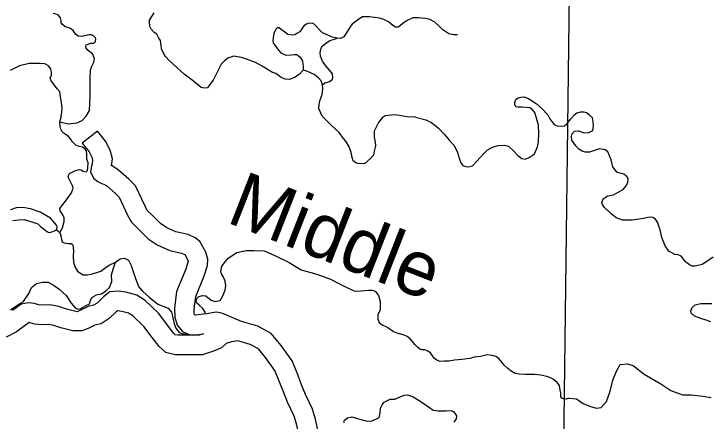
# Model space of a CAD drawing. Extents: x 8749 to 11879, y 13275 to 15339.
# Drawn here: x 9703.5 to 9809.8, y 14207.1 to 14269.4 of the extents above; entities that cross this region are included whole.
import ezdxf

# ---------------------------------------------------------------- set-up
doc = ezdxf.new("R2010")
doc.units = 0
for name, color, linetype in [('Level 35', 7, 'Continuous'), ('Level 46', 7, 'Continuous'), ('Level 5', 7, 'Continuous')]:
    doc.layers.add(name, color=color, linetype=linetype)

msp = doc.modelspace()

# ---------------------------------------------------------------- linework, layer by layer
at = {"layer": 'Level 35'}
for points in [[(9710.56, 14252.92), (9711.82, 14252.57), (9713.12, 14252.73), (9713.94, 14253.11), (9714.55, 14253.75), (9715.07, 14254.65), (9715.17, 14256.86), (9715.17, 14259.71), (9715.23, 14260.79), (9715.43, 14261.39), (9715.75, 14262.03), (9715.85, 14262.61), (9715.53, 14263.31), (9714.89, 14263.81), (9714.59, 14264.19), (9714.53, 14264.4), (9714.53, 14264.46), (9714.57, 14264.68), (9714.87, 14264.8), (9715.23, 14264.92), (9715.75, 14264.92), (9716.01, 14265.2), (9716.07, 14265.54), (9715.99, 14265.76), (9715.69, 14266.04), (9715.35, 14266.22), (9715.03, 14266.22), (9714.79, 14266.18), (9714.39, 14266.08), (9713.86, 14265.98), (9713.38, 14266.02), (9712.98, 14266.28), (9712.78, 14266.56), (9712.56, 14266.88), (9712.2, 14267.16), (9711.78, 14267.32), (9711.35, 14267.42), (9710.97, 14267.77), (9710.75, 14268.05), (9710.77, 14268.39), (9710.65, 14268.81), (9710.29, 14269.25), (9709.93, 14269.37), (9709.51, 14269.47)], [(9729.55, 14260.17), (9728.4, 14261.26), (9727.33, 14262.25), (9726.69, 14262.91), (9726.33, 14263.51), (9726.09, 14264.05), (9726.03, 14264.57), (9725.93, 14265.32), (9725.7, 14265.72), (9725.38, 14266.3), (9724.96, 14266.58), (9724.5, 14267.07), (9724.36, 14267.39), (9724.3, 14267.67), (9724.24, 14268.05), (9724.28, 14268.45), (9724.64, 14269.03), (9724.98, 14269.57)], [(9756.82, 14268.94), (9756.26, 14268.6), (9755.23, 14267.83), (9754.97, 14267.43), (9754.43, 14266.61), (9753.99, 14265.91), (9753.46, 14265.65), (9752.94, 14265.69), (9752.2, 14265.83), (9751.44, 14266.21), (9750.71, 14266.53), (9750.25, 14266.95), (9749.81, 14267.47), (9749.39, 14267.87), (9749.11, 14267.97), (9748.54, 14267.95), (9748.28, 14267.85), (9747.86, 14267.61), (9747.56, 14267.15), (9747.24, 14266.69), (9746.78, 14266.39), (9746.5, 14266.21), (9746.2, 14266.17)], [(9771.38, 14266.23), (9770.82, 14266.23), (9770.02, 14266.35), (9769.11, 14266.95), (9768.59, 14267.49), (9767.87, 14268.17), (9767.15, 14268.56), (9766.42, 14268.72), (9765.38, 14268.8), (9764.54, 14268.82), (9763.67, 14268.42), (9763.01, 14267.93), (9762.37, 14267.45), (9762.2, 14267.39), (9761.9, 14267.37), (9761.46, 14267.65), (9760.81, 14268.21), (9760.09, 14268.56), (9759.41, 14268.78), (9757.9, 14268.98), (9756.82, 14268.94)], [(9746.2, 14266.17), (9745.43, 14266.27), (9744.93, 14266.61), (9744.39, 14267.02), (9744.07, 14267.26), (9743.79, 14267.26), (9743.56, 14267.06), (9743.28, 14266.39), (9743.16, 14265.73), (9743.12, 14265.33), (9743.16, 14265.01), (9743.44, 14264.65), (9744.01, 14263.85), (9744.35, 14263.48), (9745.09, 14263.1), (9745.91, 14263.14), (9746.36, 14263.2), (9746.74, 14263.22), (9746.8, 14263.21)], [(9750.73, 14258.58), (9751.05, 14258.86), (9751.82, 14259.08), (9752.22, 14259.44), (9752.28, 14259.74), (9752.24, 14260.22), (9751.82, 14260.76), (9751.19, 14261.51), (9750.69, 14262.19), (9750.43, 14262.97), (9750.37, 14263.47), (9750.45, 14264.01), (9750.63, 14264.41), (9751.15, 14264.86), (9751.86, 14265.32), (9752.56, 14265.54), (9752.94, 14265.69)], [(9746.8, 14263.21), (9747.3, 14262.78), (9747.68, 14262.2), (9747.76, 14261.36), (9747.76, 14260.82), (9747.22, 14260.21), (9746.52, 14259.71), (9745.69, 14259.39), (9744.99, 14259.41), (9744.39, 14259.69), (9743.58, 14260.29), (9743.06, 14260.46), (9741.48, 14261.4), (9740.45, 14262), (9739.07, 14262.48), (9738.34, 14262.74), (9737.72, 14262.86), (9737.12, 14262.92), (9736.7, 14262.8), (9736.23, 14262.62), (9735.69, 14262.18), (9735.21, 14261.7), (9734.55, 14260.4), (9733.98, 14259.25), (9733.48, 14258.59), (9733.12, 14258.11), (9732.64, 14258.07), (9732.18, 14258.17), (9731.53, 14258.67), (9730.59, 14259.41), (9729.55, 14260.17)], [(9710.57, 14235.97), (9710.94, 14236.68), (9711.2, 14237.67), (9711.2, 14238.23), (9710.94, 14238.79), (9710.58, 14239.27), (9710.56, 14239.65), (9710.84, 14240.04), (9711.58, 14240.94), (9712.31, 14242.02), (9712.57, 14242.74), (9712.47, 14243.11), (9712.21, 14243.63), (9711.92, 14244.21), (9711.8, 14244.57), (9712.02, 14244.97), (9712.85, 14245.41), (9713.51, 14245.59), (9713.81, 14245.57), (9714.11, 14245.37), (9714.57, 14245.27), (9714.8, 14245.45), (9714.84, 14245.89), (9714.86, 14246.6), (9714.68, 14247.21), (9714.68, 14247.92), (9714.62, 14248.48), (9714.39, 14248.78), (9714.01, 14249.02), (9713.51, 14249.1), (9712.97, 14249.34), (9712.49, 14249.84), (9712.17, 14250.32), (9711.84, 14250.72), (9711.38, 14250.99), (9711.04, 14251.21), (9710.96, 14251.31), (9710.7, 14251.76), (9710.6, 14252.18), (9710.56, 14252.92), (9710.76, 14253.62), (9710.88, 14254.91), (9710.82, 14255.91), (9710.66, 14256.71), (9710.56, 14257.47), (9710.16, 14257.96), (9709.59, 14258.71), (9709.21, 14259.17), (9709.09, 14259.59), (9709.25, 14260.05), (9709.27, 14260.37), (9709.17, 14261.01), (9708.81, 14261.49), (9708.26, 14261.76), (9707.46, 14261.82), (9705.83, 14261.8), (9704.37, 14261.49), (9702.96, 14260.75)], [(9750.31, 14256.12), (9750.67, 14257.09), (9750.75, 14257.93), (9750.73, 14258.58), (9750.53, 14259.16), (9750.09, 14259.64), (9749.43, 14260.12), (9748.34, 14260.64), (9747.76, 14260.82)], [(9764.93, 14253.63), (9763.61, 14253.67), (9762.48, 14253.87), (9761.66, 14253.95), (9761.14, 14253.93), (9760.29, 14253.81), (9759.83, 14253.49), (9759.29, 14252.77), (9758.61, 14251.46), (9758.63, 14250.54), (9758.79, 14249.8), (9758.81, 14249.21), (9758.63, 14248.41), (9758.53, 14247.81), (9758.06, 14247.29), (9757.2, 14246.53), (9756.6, 14246.45), (9756.14, 14246.53), (9755.79, 14246.61), (9755.41, 14246.91), (9755.25, 14247.43), (9755.11, 14248.21), (9754.77, 14249.07), (9754.27, 14249.92), (9753.93, 14250.36), (9753.24, 14251.28), (9752.06, 14252.38), (9751.15, 14253.25), (9750.67, 14253.77), (9750.35, 14254.47), (9750.17, 14254.93), (9750.19, 14255.51), (9750.31, 14256.12)], [(9779.14, 14249.17), (9779.93, 14248.47), (9780.61, 14247.75), (9781.2, 14247.28), (9781.68, 14247.2), (9782.12, 14247.34), (9782.24, 14247.38), (9783.12, 14248.01), (9783.57, 14249.07), (9783.73, 14249.85), (9783.81, 14251.1), (9783.75, 14252.4), (9783.43, 14253.44), (9783.18, 14254.33), (9782.82, 14254.71), (9782.42, 14255.03), (9781.9, 14255.09), (9781.24, 14255.13), (9780.61, 14255.13), (9780.27, 14255.21), (9780.13, 14255.53), (9780.15, 14255.93), (9780.29, 14256.29), (9780.65, 14256.59), (9781.04, 14256.67), (9781.5, 14256.71), (9782.24, 14256.47), (9783.39, 14255.69), (9784.25, 14254.95), (9785.15, 14253.99), (9785.49, 14253.38), (9785.92, 14252.76), (9786.14, 14252.48), (9786.58, 14252.28), (9787.22, 14252.24), (9787.72, 14252.28), (9788.15, 14252.64), (9788.69, 14253.38), (9789.17, 14253.85)], [(9794.85, 14247.09), (9794.33, 14248.29), (9793.96, 14248.61), (9793.07, 14248.75), (9792.31, 14248.51), (9791.53, 14248.26), (9790.86, 14248.26), (9790.42, 14248.4), (9789.91, 14248.7), (9789.48, 14249.23), (9788.83, 14250.07), (9788.81, 14250.61), (9788.83, 14250.99), (9789.26, 14251.47), (9789.86, 14251.53), (9790.72, 14251.23), (9791.42, 14251.26), (9792.04, 14251.58), (9792.15, 14252.26), (9792.12, 14252.9), (9791.99, 14253.5), (9791.48, 14253.96), (9791.07, 14254.28), (9790.75, 14254.36), (9790.15, 14254.36), (9789.59, 14254.2), (9789.17, 14253.85)], [(9764.93, 14253.63), (9766.51, 14253.2), (9767.4, 14252.78), (9768.44, 14251.94), (9769.38, 14250.96), (9770.07, 14250.11), (9770.83, 14249.27), (9771.35, 14248.19), (9771.67, 14247.16), (9771.89, 14246.6), (9772.2, 14246.24), (9772.66, 14246.04), (9773.02, 14246.02), (9773.64, 14246.16), (9774.3, 14246.9), (9775.37, 14248.03), (9775.91, 14248.55), (9776.69, 14249.03), (9777.6, 14249.29), (9778.56, 14249.33), (9779.14, 14249.17)], [(9804.58, 14232.61), (9803.66, 14233.09), (9803.12, 14233.92), (9802.61, 14235.22), (9802.37, 14236.38), (9802.1, 14237.08), (9801.99, 14237.43), (9801.64, 14238), (9801.21, 14238.27), (9800.67, 14238.29), (9799.81, 14238.11), (9798.81, 14237.94), (9798.05, 14237.86), (9796.6, 14237.86), (9795.65, 14238.21), (9794.87, 14238.81), (9793.85, 14239.78), (9793.52, 14240.26), (9793.44, 14240.56), (9793.63, 14241.13), (9794.36, 14241.56), (9795.22, 14241.75), (9795.92, 14242.13), (9796.68, 14242.56), (9797.08, 14243.04), (9797.43, 14243.61), (9797.46, 14244.1), (9797.33, 14244.47), (9796.81, 14244.88), (9796.19, 14245.04), (9795.73, 14245.18), (9795.47, 14245.53), (9795.14, 14245.99), (9795.03, 14246.44), (9794.85, 14247.09)], [(9703.38, 14237.78), (9704.26, 14237.92), (9705.11, 14237.94), (9706.09, 14237.64), (9707.16, 14237.3), (9707.6, 14236.88), (9708.2, 14236.44), (9708.56, 14236.1), (9708.88, 14235.98), (9709.18, 14236.02), (9709.71, 14236.2), (9710.03, 14236.38), (9710.15, 14236.74), (9710.07, 14237.06), (9709.14, 14238.17), (9707.54, 14239.07), (9706.05, 14239.61), (9704.87, 14239.77), (9703.87, 14239.76), (9703.02, 14239.45)], [(9710.03, 14236.38), (9710.57, 14235.97), (9710.75, 14235.31), (9710.79, 14234.91), (9710.89, 14234.55), (9711.21, 14234.37), (9711.84, 14234.27), (9712.3, 14234.29), (9712.48, 14234.15), (9712.6, 14233.89), (9712.58, 14233.56), (9712.62, 14233.2), (9712.56, 14232.3), (9712.66, 14231.45), (9712.82, 14230.73), (9713.27, 14230.07), (9713.61, 14229.77), (9714.13, 14229.47), (9714.77, 14229.47), (9715.35, 14229.59), (9716.18, 14229.83), (9716.8, 14230.03), (9717.44, 14230.49), (9718.09, 14230.97), (9719.05, 14231.45)], [(9735.19, 14230.02), (9735.32, 14230.83), (9736.29, 14232.02), (9737.62, 14232.89), (9739.05, 14233.21), (9740.27, 14233.21), (9741.77, 14233.17), (9743.4, 14232.47), (9745.6, 14231.36), (9747.45, 14230.27), (9749.85, 14229.58), (9751.94, 14228.81), (9753.23, 14228.15), (9754.35, 14227.59), (9755.67, 14226.99), (9756.61, 14227.06), (9757.8, 14227.13), (9758.32, 14227.13), (9758.77, 14226.99), (9759.3, 14226.3), (9759.51, 14225.42), (9759.54, 14224.1), (9759.16, 14223.44), (9759.16, 14222.7), (9759.4, 14222.18), (9759.82, 14221.83), (9760.73, 14221.41), (9761.56, 14220.82), (9762.33, 14220.49)], [(9810.48, 14232.18), (9809.78, 14231.75), (9808.76, 14231.07), (9807.73, 14230.83), (9807.25, 14230.83), (9806.84, 14231.02), (9806.22, 14231.5), (9805.79, 14232.07), (9805.55, 14232.34), (9805.12, 14232.53), (9804.58, 14232.61)], [(9719.05, 14231.45), (9719.78, 14231.94), (9720.44, 14232.05), (9721.07, 14231.73), (9721.45, 14230.93), (9722.08, 14229.08), (9722.6, 14227.72), (9723.2, 14226.99), (9724.21, 14226.08), (9725.53, 14225), (9727.13, 14224.37), (9727.61, 14223.76), (9727.8, 14223.17), (9727.99, 14222.2), (9728.23, 14221.44), (9728.53, 14220.95), (9728.8, 14220.68), (9729.24, 14220.51), (9729.62, 14220.44), (9730.3, 14220.37)], [(9703.02, 14224.11), (9704.26, 14224.98), (9704.97, 14225.4), (9705.81, 14226.64), (9706.23, 14227.54), (9706.99, 14228.17), (9707.9, 14228.38), (9708.77, 14228.38), (9709.68, 14227.86), (9710.45, 14227.3), (9711.53, 14226.32), (9712.29, 14225.14), (9712.87, 14224.43), (9713.3, 14224.21), (9713.8, 14224.33), (9713.9, 14224.43), (9714.65, 14224.83), (9715.05, 14225.02), (9715.15, 14225.21), (9715.22, 14225.56), (9715.46, 14226.04), (9716.16, 14226.43), (9716.93, 14226.57), (9717.56, 14227.06), (9718.15, 14227.54), (9718.5, 14228.49), (9718.43, 14229.5), (9718.71, 14230.34), (9719.05, 14231.45)], [(9732.7, 14223.5), (9732.78, 14223.78), (9732.4, 14224.33), (9731.84, 14224.82), (9731.5, 14225.16), (9731.4, 14225.4), (9731.49, 14225.87), (9731.81, 14226.15), (9732.36, 14226.32), (9732.89, 14226.25), (9733.69, 14225.59), (9734.31, 14225.42), (9735.05, 14225.56), (9735.47, 14226.25), (9735.85, 14227.13), (9735.92, 14227.86), (9735.85, 14228.52), (9735.57, 14229.15), (9735.29, 14229.64), (9735.19, 14230.02)], [(9810.08, 14222.28), (9809.4, 14222.57), (9808.59, 14222.79), (9807.62, 14223.14), (9807.08, 14223.6), (9807.03, 14224), (9807.25, 14224.49), (9807.73, 14224.89), (9808.57, 14225.11), (9809.65, 14225.11), (9810.24, 14225.11)], [(9788.41, 14210.6), (9787.96, 14210.44), (9787.6, 14210.5), (9787.34, 14210.62), (9787.16, 14210.84), (9787.14, 14211.04), (9787.14, 14211.44), (9787.06, 14211.86), (9786.94, 14212.54), (9786.58, 14213), (9786, 14213.53), (9785.25, 14213.89), (9784.13, 14214.11), (9783.18, 14214.23), (9781.78, 14214.25), (9780.79, 14214.31), (9780.19, 14214.39), (9779.55, 14214.75), (9779.07, 14215.13), (9778.5, 14215.67), (9778, 14216.34), (9777.64, 14216.72), (9777.24, 14217), (9776.68, 14217.16), (9775.91, 14217.22), (9774.89, 14217), (9773.93, 14216.88), (9773.24, 14216.66), (9772.01, 14216.54), (9770.89, 14216.42), (9770.1, 14216.3), (9769.38, 14216.28), (9768.68, 14216.24), (9768.18, 14216.42), (9767.81, 14216.72), (9767.63, 14216.96), (9767.41, 14217.26), (9767.25, 14217.56), (9766.83, 14217.82), (9766.39, 14218), (9765.93, 14218.02), (9765.55, 14218.18), (9765.24, 14218.4), (9764.82, 14218.84), (9764.44, 14219.32), (9764.1, 14219.67), (9763.64, 14220.05), (9763.18, 14220.27), (9762.33, 14220.49)], [(9788.41, 14210.6), (9789.56, 14210.51), (9790.6, 14209.8), (9791.69, 14209.33), (9792.63, 14209.09), (9793.34, 14209.19), (9794.14, 14210.13), (9794.71, 14211.69), (9795.13, 14213.39), (9795.7, 14214.76), (9796.22, 14215.75), (9797.3, 14215.89), (9798.25, 14215.61), (9799.9, 14214.29), (9802.44, 14212.82), (9804, 14211.78), (9805.75, 14211.12), (9807.11, 14211.12), (9808.86, 14210.93), (9810.13, 14210.74)], [(9754, 14206.88), (9754.1, 14207.23), (9754.55, 14207.61), (9755.18, 14207.75), (9756.23, 14207.47), (9757.55, 14207.09), (9758.32, 14207.16), (9759.36, 14207.65), (9759.54, 14208.35), (9759.57, 14209.08), (9759.82, 14209.6), (9760.13, 14210.02), (9761.04, 14210.44), (9761.77, 14210.48), (9762.57, 14210.82), (9763.2, 14211.07), (9763.72, 14211.1), (9764.56, 14210.82), (9765.77, 14210.09), (9767.1, 14209.18), (9767.62, 14208.8), (9768.42, 14208.66), (9769.64, 14208.7), (9770.41, 14208.73), (9770.76, 14208.56), (9771, 14208.24), (9771.21, 14207.89), (9771.17, 14207.44), (9770.82, 14206.95)]]:
    msp.add_lwpolyline(points, dxfattribs=at)
at = {"layer": 'Level 46'}
for points in [[(9722.14, 14243.09), (9721.1, 14244.13), (9719.53, 14245.48), (9718.53, 14246.15), (9718.47, 14246.17), (9718.59, 14247.24), (9718.25, 14248.55), (9717.55, 14249.93), (9716.32, 14251.47), (9713.97, 14249.61)], [(9713.97, 14249.61), (9715.01, 14248.3), (9715.43, 14247.47), (9715.55, 14247.02), (9715.49, 14246.46), (9715.4, 14246.1), (9715.23, 14245.25), (9715.7, 14244.3), (9716.34, 14243.76), (9716.9, 14243.48), (9717.28, 14243.38), (9717.71, 14243.09), (9719.06, 14241.93), (9719.64, 14241.35)], [(9750.1, 14205.19), (9749.65, 14207.42), (9749.18, 14208.92), (9748.13, 14211.18), (9747.52, 14212.65), (9747, 14214.08), (9746.06, 14216.32), (9744.39, 14218.65), (9742.86, 14220.5), (9740.81, 14221.64), (9738.34, 14222.34), (9735.32, 14223.61), (9734.45, 14223.79), (9732.97, 14223.53), (9731.27, 14223.31), (9731.18, 14223.31), (9731.11, 14223.53), (9731.07, 14224.28), (9731.32, 14226.16), (9732.62, 14229.34), (9733.12, 14230.91), (9733.16, 14231.89), (9732.89, 14232.97), (9731.95, 14234.6), (9731.25, 14235.14), (9730.16, 14235.66), (9728.3, 14236.08), (9726.9, 14236.7), (9725.94, 14237.34), (9724.7, 14238.58), (9723.92, 14239.35), (9723.57, 14239.99), (9722.14, 14243.09)], [(9719.64, 14241.35), (9720.89, 14238.64), (9721.5, 14237.52), (9722.59, 14236.45), (9724.03, 14235.01), (9725.45, 14234.06), (9727.35, 14233.22), (9729.17, 14232.81), (9729.65, 14232.58), (9730.08, 14231.84), (9730.15, 14231.58), (9730.14, 14231.43), (9729.8, 14230.37), (9728.39, 14226.94), (9728.06, 14224.39), (9728.14, 14223), (9728.51, 14221.77), (9729.32, 14220.83), (9730.3, 14220.36), (9731.37, 14220.29), (9732.52, 14220.45)], [(9732.52, 14220.45), (9731.86, 14220.23), (9730.51, 14220.23), (9728.59, 14220.23), (9728.2, 14220.33), (9727.94, 14220.56), (9727.07, 14221.73), (9725.61, 14223.6), (9723.6, 14225.54), (9722.32, 14226.39), (9720.66, 14226.83), (9719.46, 14227.01), (9718.21, 14226.87), (9717.21, 14226.1), (9716.23, 14225.16), (9715.71, 14224.82), (9714.9, 14224.66), (9713.61, 14224.01), (9713.19, 14223.84)], [(9713.19, 14223.84), (9711.58, 14224.24), (9710.39, 14224.65), (9709.06, 14224.88), (9707.93, 14224.84), (9707.3, 14224.89), (9706.66, 14225.09), (9705.76, 14225.21), (9704.63, 14225), (9703.32, 14224.05)], [(9737.77, 14219.39), (9736.82, 14219.21), (9735.99, 14219), (9735.28, 14218.34), (9734.03, 14217.79), (9732.35, 14217.23), (9730.51, 14217.23), (9728.19, 14217.23), (9726.74, 14217.62), (9725.72, 14218.52), (9724.68, 14219.91), (9723.38, 14221.59), (9721.71, 14223.19), (9721.07, 14223.62), (9720.04, 14223.89), (9719.4, 14223.99), (9719.37, 14223.98), (9719.17, 14223.83), (9718.1, 14222.79), (9716.85, 14221.99), (9715.89, 14221.8), (9714.86, 14221.28), (9713.92, 14220.9), (9712.51, 14220.92)], [(9712.51, 14220.92), (9710.72, 14221.37), (9709.65, 14221.74), (9708.86, 14221.87), (9707.86, 14221.83), (9706.72, 14221.93), (9706.01, 14222.15), (9705.85, 14222.17), (9705.1, 14221.63), (9703.9, 14220.74), (9702.35, 14219.97)], [(9747.33, 14204.03), (9746.74, 14206.67), (9746.37, 14207.84), (9745.38, 14209.98), (9744.73, 14211.56), (9744.2, 14212.98), (9743.43, 14214.85), (9742.01, 14216.82), (9740.91, 14218.15), (9739.65, 14218.85), (9737.77, 14219.39)]]:
    msp.add_lwpolyline(points, dxfattribs=at)
at = {"layer": 'Level 5'}
msp.add_lwpolyline([(9788.79, 14301.19), (9787.48, 14194.98)], dxfattribs=at)

# ---------------------------------------------------------------- texts
at = {"layer": 'Level 35'}
msp.add_text('Middle', height=8.448, rotation=338.6096, dxfattribs=at).set_placement((9735.79, 14237.61))

doc.saveas('drawing.dxf')
